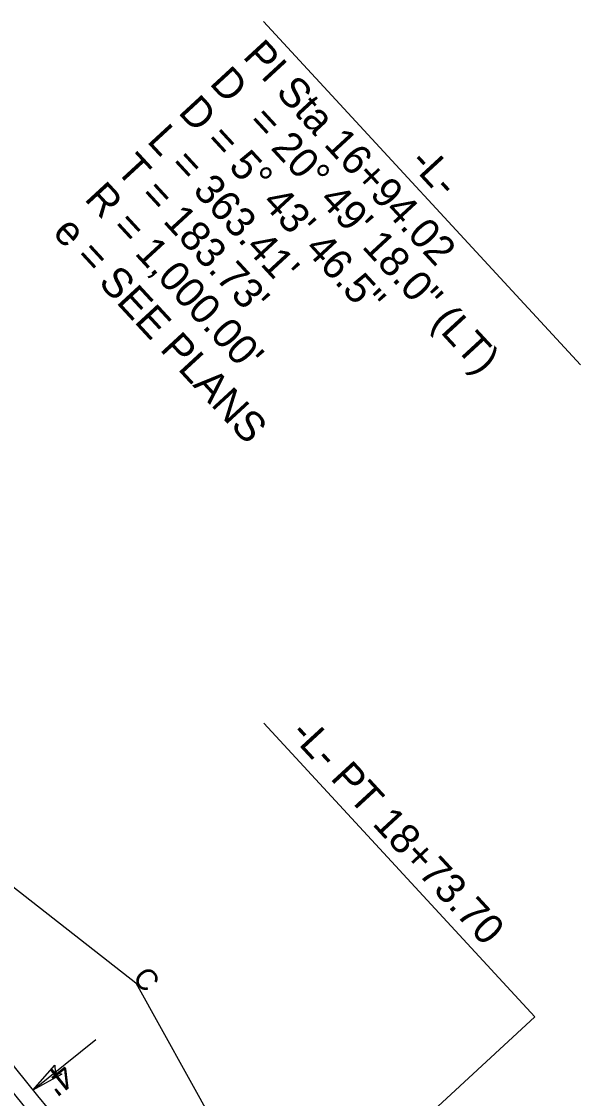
# Model space of a CAD drawing. Extents: x 1702862 to 1704514, y 793768 to 796215.
# Drawn here: x 1703216.2 to 1703347.5, y 795384 to 795637.1 of the extents above; entities that cross this region are included whole.
import ezdxf

# ---------------------------------------------------------------- set-up
doc = ezdxf.new("R2010")
doc.units = 0
for name, color, linetype in [('Prop Dimension', 7, 'Continuous'), ('Prop EOT', 7, 'Continuous'), ('Prop Horizontal Alignment', 7, 'Continuous'), ('Prop Horizontal Alignment Curve and Spiral Data', 7, 'Continuous'), ('Prop Horizontal Alignment Station Label', 7, 'Continuous'), ('Prop Paved Shoulder', 7, 'Continuous'), ('Prop SS Cut Line', 7, 'Continuous'), ('Prop SS Misc', 7, 'Continuous'), ('Prop Terminator CELL', 7, 'Continuous')]:
    doc.layers.add(name, color=color, linetype=linetype)

msp = doc.modelspace()

# ---------------------------------------------------------------- linework, layer by layer
at = {"layer": 'Prop Dimension'}
msp.add_line((1703218.85, 795385.94), (1703233.69, 795397.85), dxfattribs=at)
at = {"layer": 'Prop EOT'}
msp.add_arc((1703981.48, 795998.22), 982, 215.01075, 222.70907, dxfattribs=at)
at = {"layer": 'Prop Horizontal Alignment'}
msp.add_arc((1703981.48, 795998.22), 1000, 201.8874, 222.70907, dxfattribs=at)
at = {"layer": 'Prop Horizontal Alignment Curve and Spiral Data'}
msp.add_line((1703273.02, 795637.09), (1703347.53, 795556.37), dxfattribs=at)
at = {"layer": 'Prop Horizontal Alignment Station Label'}
for p in [(1703273.17, 795472.15), (1703247.78, 795320.96)]:
    msp.add_line(p, (1703336.84, 795403.17), dxfattribs=at)
at = {"layer": 'Prop Paved Shoulder'}
msp.add_arc((1703981.48, 795998.22), 978, 215.01075, 222.70907, dxfattribs=at)
at = {"layer": 'Prop SS Cut Line'}
for p, q in [((1703204.36, 795441.41), (1703243.06, 795411.13)), ((1703243.06, 795411.13), (1703266.46, 795368.92))]:
    msp.add_line(p, q, dxfattribs=at)
at = {"layer": 'Prop Terminator CELL'}
msp.add_lwpolyline([(1703225.64, 795389.7), (1703218.85, 795385.94), (1703224, 795391.82), (1703224.09, 795390.14)], close=True, dxfattribs=at)

# ---------------------------------------------------------------- texts
at = {"layer": 'Prop Dimension'}
msp.add_text("4'", height=6, rotation=218.7502, dxfattribs=at).set_placement((1703225.63, 795392.67))
at = {"layer": 'Prop Horizontal Alignment Curve and Spiral Data'}
for s, p in [('PI Sta 16+94.02', (1703267.96, 795628.72)), ('D', (1703260.15, 795622.44)), ('D = 5%%d 43\' 46.5"', (1703252.8, 795615.65)), ('= 20%%d 49\' 18.0" (LT)', (1703269.08, 795613.19)), ("L = 363.41'", (1703245.46, 795608.87)), ("T = 183.73'", (1703238.11, 795602.09)), ('-L-', (1703307.07, 795603.74)), ("R = 1,000.00'", (1703230.76, 795595.3)), ('e = SEE PLANS', (1703223.26, 795587.3))]:
    msp.add_text(s, height=7, rotation=312.7091, dxfattribs=at).set_placement(p)
at = {"layer": 'Prop Horizontal Alignment Station Label'}
msp.add_text('-L- PT 18+73.70', height=7, rotation=312.7091, dxfattribs=at).set_placement((1703279.02, 795469.43))
at = {"layer": 'Prop SS Misc'}
msp.add_text('C', height=5, rotation=308.4864, dxfattribs=at).set_placement((1703242.1, 795412.34))

doc.saveas('drawing.dxf')
